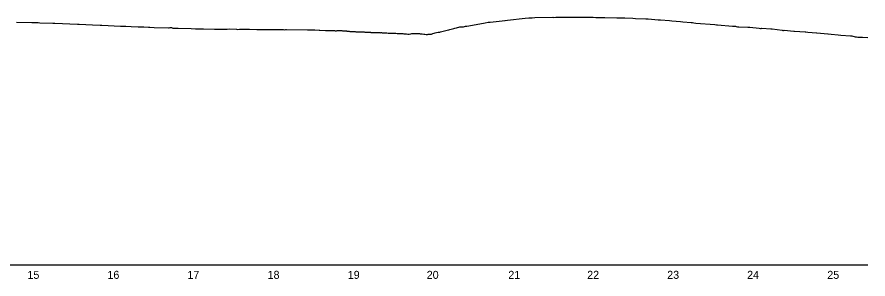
# Model space of a CAD drawing. Extents: x 1778432 to 1784301, y 601022 to 621789.
# Drawn here: x 1780624 to 1781686, y 618022 to 618349 of the extents above; entities that cross this region are included whole.
import ezdxf

# ---------------------------------------------------------------- set-up
doc = ezdxf.new("R2010")
doc.units = 0
for name, color, linetype in [('Exist Profile Cell', 7, 'Continuous'), ('Exist Vertical Profile Ground Line', 7, 'Continuous'), ('Exist Vertical Profile Horizontal Axis Label Major', 7, 'Continuous')]:
    doc.layers.add(name, color=color, linetype=linetype)

msp = doc.modelspace()

# ---------------------------------------------------------------- linework, layer by layer
at = {"layer": 'Exist Profile Cell'}
msp.add_line((1780143, 618039.2), (1781686.3, 618039.2), dxfattribs=at)
at = {"layer": 'Exist Vertical Profile Ground Line'}
for points in [[(1780623.1, 618342), (1780642, 618341.6), (1780648.7, 618341.6), (1780649.1, 618341.5), (1780649.9, 618341.5), (1780652.1, 618341.4), (1780668.6, 618340.7), (1780669.3, 618340.7), (1780670.9, 618340.9), (1780699.1, 618339.6), (1780699.4, 618339.6), (1780701.1, 618339.6), (1780718, 618338.9), (1780727.5, 618338.3), (1780728, 618338.3), (1780729.6, 618338.2), (1780753, 618337.2), (1780757.3, 618337), (1780757.6, 618337), (1780758.2, 618337), (1780759.5, 618337), (1780766.2, 618336.7), (1780774.9, 618336.4), (1780777.6, 618336.3), (1780780.9, 618336.2), (1780782, 618336.1), (1780787.8, 618335.8), (1780789.7, 618335.7), (1780794.8, 618335.6), (1780812.7, 618334.9), (1780813.7, 618335.2), (1780815, 618335.3), (1780816.6, 618335.3), (1780818.1, 618334.8), (1780820.3, 618334.7), (1780824.9, 618334.5), (1780841.2, 618334.1), (1780846.4, 618333.9), (1780856.4, 618333.7), (1780870.3, 618333.5), (1780870.9, 618333.5), (1780871.9, 618333.4), (1780875, 618333.3), (1780886, 618333.4), (1780889.4, 618333.6), (1780897.6, 618333.3), (1780898.7, 618333.1), (1780901.3, 618333.3), (1780914.2, 618333.2), (1780923, 618333.1), (1780927.8, 618333.1), (1780928.8, 618333), (1780930.8, 618333), (1780936.9, 618332.9), (1780956.2, 618332.8), (1780957.1, 618332.7), (1780958.8, 618332.8), (1780960.4, 618332.8), (1780986.4, 618332.6), (1780987.3, 618332.6), (1780988.4, 618332.5), (1780992.3, 618332.5), (1780993.3, 618332.5), (1780995.4, 618332.4), (1781001, 618332.3), (1781001.9, 618332.2), (1781009.1, 618331.9), (1781009.9, 618331.9), (1781013, 618331.8), (1781018.5, 618331.6), (1781019.4, 618331.5), (1781020.2, 618331.5), (1781021, 618331.4), (1781021.8, 618331.4)], [(1781106.7, 618327.7), (1781108.3, 618327.5), (1781110, 618327.4), (1781111.6, 618327.2), (1781112, 618327.1), (1781112.7, 618327.1), (1781113.2, 618327.2), (1781114.9, 618327.5), (1781115.2, 618327.6), (1781115.5, 618327.7), (1781116.5, 618327.8), (1781118.2, 618327.8), (1781119.8, 618327.9), (1781121.4, 618328), (1781122.7, 618328.1), (1781123.1, 618328.1), (1781124.7, 618328.1), (1781125.8, 618328), (1781126.4, 618327.9), (1781127.2, 618327.7), (1781128, 618327.6), (1781129.6, 618327.4), (1781131.5, 618327.2), (1781132.9, 618327.1), (1781134.6, 618326.9), (1781135.6, 618326.9), (1781136.2, 618326.9), (1781137, 618327.2), (1781137.8, 618327.2), (1781139.5, 618327.1), (1781140.4, 618327.1), (1781140.7, 618327.2), (1781141.1, 618327.3), (1781142.8, 618327.8), (1781144.5, 618328.3), (1781146, 618328.7), (1781147.7, 618329.1), (1781149.5, 618329.5), (1781151, 618329.6), (1781151.5, 618329.6), (1781152.6, 618329.9), (1781154.2, 618330.3), (1781155.9, 618330.7), (1781157.5, 618331.1), (1781159.2, 618331.6), (1781160.8, 618332), (1781163, 618332.6), (1781164.1, 618332.9), (1781165.7, 618333.3), (1781167.4, 618333.7), (1781169, 618334.2), (1781170.6, 618334.6), (1781172.3, 618335), (1781173.9, 618335.5), (1781175.6, 618335.9), (1781176.5, 618336.1), (1781177.6, 618336.4), (1781181.1, 618336.4), (1781183.7, 618336.9), (1781185.3, 618337.2), (1781206.4, 618340.7), (1781208.4, 618341.3), (1781212, 618341.9), (1781213.6, 618342), (1781214.6, 618342.1), (1781229.4, 618343.8), (1781232.8, 618344.1), (1781233.2, 618344.3), (1781236.3, 618344.7), (1781258.2, 618347.2), (1781262.7, 618347.5), (1781263.1, 618347.5), (1781264, 618347.4), (1781267, 618347.7), (1781270.4, 618347.8), (1781292.6, 618348.3), (1781293.9, 618348), (1781296.5, 618348.3), (1781306.7, 618348.5), (1781310.5, 618348.3), (1781322.1, 618348.5), (1781323.8, 618348.5), (1781326, 618348.5), (1781343, 618348.2), (1781346.4, 618348.1), (1781347, 618348), (1781350.6, 618347.9), (1781357.6, 618347.8), (1781372.7, 618347.6), (1781376.2, 618347.6), (1781376.5, 618347.5), (1781379, 618347.4), (1781380.6, 618347.4), (1781382.5, 618347.3), (1781392.7, 618346.9), (1781396, 618346.8), (1781408.9, 618346.3), (1781410.5, 618346.2), (1781411.9, 618346.2), (1781424.3, 618345.2), (1781427.4, 618344.9)], [(1781427.4, 618344.9), (1781438.5, 618344), (1781441.5, 618343.7), (1781452.3, 618342.8), (1781455.3, 618342.5), (1781465.7, 618341.6), (1781467.2, 618341.5), (1781468.7, 618341.4), (1781471.4, 618341), (1781495.1, 618339), (1781497.2, 618338.9), (1781498.4, 618338.7), (1781517.3, 618337), (1781521, 618337), (1781521.8, 618336.7), (1781523.4, 618336.4), (1781525, 618336.4), (1781536.2, 618335.9), (1781538.9, 618335.7), (1781550.5, 618334.5), (1781551.9, 618334.2), (1781552.9, 618334.2), (1781553.8, 618334.4), (1781564.9, 618333.8), (1781566.8, 618333.7), (1781579.2, 618332.1), (1781580, 618331.9), (1781580.8, 618331.9), (1781581.5, 618332.3), (1781593.6, 618330.9), (1781594.7, 618330.9), (1781607.9, 618329.9), (1781608.4, 618329.9), (1781608.7, 618329.9), (1781611.1, 618329.8), (1781622.2, 618328.6), (1781622.6, 618328.6), (1781636.3, 618327.6), (1781636.6, 618327.6), (1781640.5, 618327.2), (1781649, 618326.3), (1781652.3, 618325.9), (1781664.5, 618325.1), (1781666, 618324.9), (1781670.4, 618323.8), (1781672, 618323.7), (1781673.7, 618323.2), (1781674.2, 618323.2), (1781674.7, 618323.3), (1781676.6, 618323.2), (1781677.9, 618323.4), (1781678.4, 618323.4), (1781679.6, 618323.4), (1781686.3, 618322.9)], [(1781021.8, 618331.4), (1781022.7, 618331.4), (1781023.5, 618331.5), (1781024.3, 618331.6), (1781024.8, 618331.6), (1781025.1, 618331.6), (1781026, 618331.6), (1781026.3, 618331.5), (1781026.8, 618331.5), (1781027.6, 618331.5), (1781028.6, 618331.5), (1781029.3, 618331.5), (1781030.1, 618331.4), (1781030.9, 618331.4), (1781031.7, 618331.3), (1781032.6, 618331.2), (1781033.4, 618331.2), (1781034.2, 618331.1), (1781035, 618331.1), (1781035.5, 618331), (1781035.9, 618331), (1781036.7, 618330.9), (1781037.5, 618330.8), (1781037.9, 618330.7), (1781038.3, 618330.7), (1781039.2, 618330.6), (1781040, 618330.6), (1781040.8, 618330.6), (1781041.6, 618330.5), (1781042.5, 618330.5), (1781043.3, 618330.4), (1781044.1, 618330.4), (1781044.9, 618330.3), (1781045.8, 618330.3), (1781046.6, 618330.2), (1781047.5, 618330.2), (1781047.8, 618330.1), (1781048.2, 618330.1), (1781049.1, 618330.1), (1781049.9, 618330.1), (1781050.7, 618330.1), (1781051.5, 618330.1), (1781051.9, 618330.1), (1781052.4, 618330.1), (1781053.2, 618330), (1781054, 618330), (1781054.8, 618330), (1781055.7, 618329.9), (1781056.5, 618329.9), (1781057.3, 618329.9), (1781058.1, 618329.8), (1781059, 618329.8), (1781059.8, 618329.8), (1781060.6, 618329.7), (1781061.4, 618329.7), (1781062.3, 618329.6), (1781063.1, 618329.6), (1781063.5, 618329.5), (1781063.9, 618329.5), (1781064.7, 618329.5), (1781065.1, 618329.5), (1781065.6, 618329.4), (1781066.4, 618329.4), (1781067.2, 618329.4), (1781068, 618329.4), (1781068.9, 618329.3), (1781069.7, 618329.3), (1781070.5, 618329.3), (1781071.3, 618329.3), (1781072.2, 618329.2), (1781073, 618329.2), (1781073.8, 618329.2), (1781074.6, 618329.2), (1781075.7, 618329.1), (1781076.3, 618329.1), (1781077.1, 618328.9), (1781077.9, 618329), (1781078.8, 618329), (1781079.6, 618328.9), (1781080.4, 618328.9), (1781081.2, 618328.9), (1781082.1, 618328.8), (1781082.9, 618328.8), (1781083.7, 618328.7), (1781084.5, 618328.7), (1781085.3, 618328.6), (1781087, 618328.5), (1781088.8, 618328.4), (1781090.3, 618328.4), (1781091.3, 618328.3), (1781091.9, 618328.3), (1781093.6, 618328.3), (1781095.4, 618328.2), (1781096.8, 618328.2), (1781098.5, 618328.1), (1781100.1, 618328), (1781100.6, 618328), (1781101.8, 618328), (1781103.4, 618327.9), (1781105.3, 618327.8), (1781106.7, 618327.7)]]:
    msp.add_lwpolyline(points, dxfattribs=at)

# ---------------------------------------------------------------- texts
at = {"layer": 'Exist Vertical Profile Horizontal Axis Label Major'}
for s, p in [('15', (1780636.7, 618021.7)), ('16', (1780736.6, 618021.7)), ('17', (1780836.5, 618021.7)), ('18', (1780936.6, 618021.7)), ('19', (1781036.7, 618021.7)), ('20', (1781135.3, 618021.7)), ('21', (1781237.2, 618021.7)), ('22', (1781335.7, 618021.7)), ('23', (1781435.6, 618021.7)), ('24', (1781535.4, 618021.7)), ('25', (1781635.5, 618021.7))]:
    msp.add_text(s, height=10, dxfattribs=at).set_placement(p)

doc.saveas('drawing.dxf')
